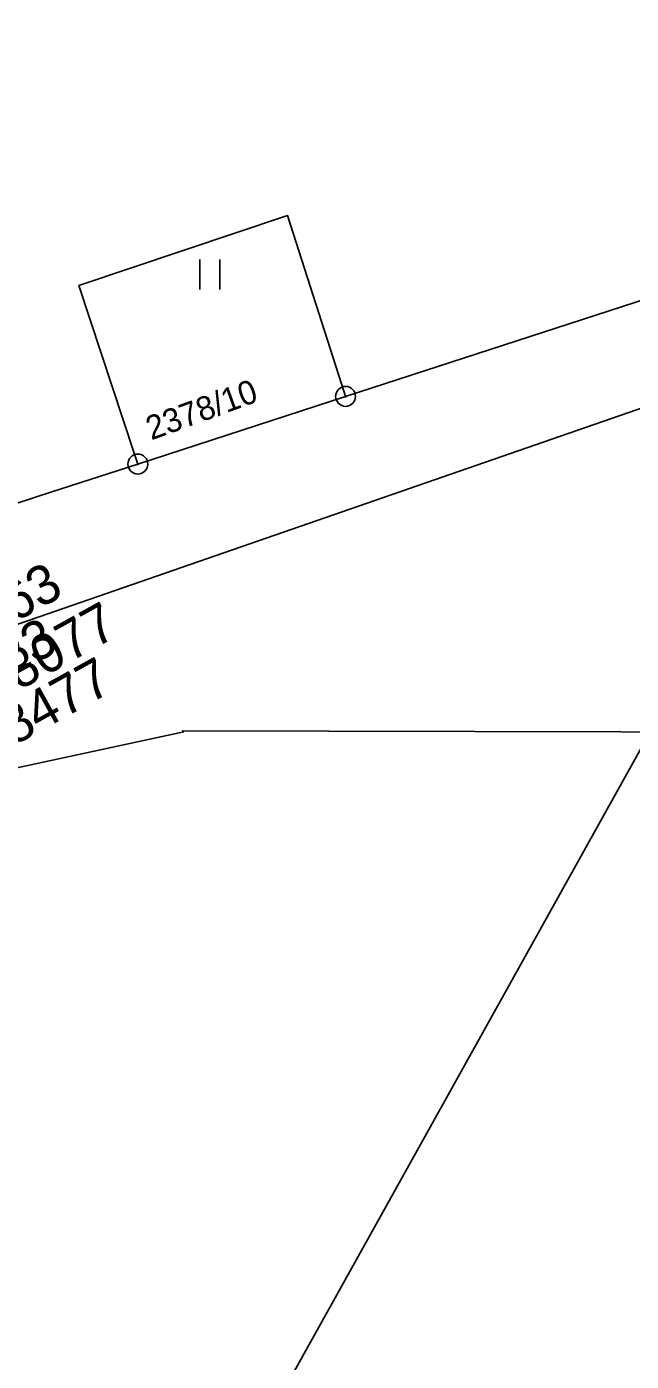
# Model space of a CAD drawing. Extents: x -483721 to -481876, y -1129170 to -1127366.
# Drawn here: x -482169.1 to -482138.7, y -1128251.9 to -1128184.8 of the extents above; entities that cross this region are included whole.
import ezdxf

# ---------------------------------------------------------------- set-up
doc = ezdxf.new("R2010")
doc.units = 0
for name, color, linetype in [('Hranice parcel', 7, 'Continuous'), ('Parcelní čísla', 7, 'Continuous'), ('u_OP_lesa', 7, 'Continuous'), ('u_vytyčení', 7, 'Continuous'), ('Značky bodu BP', 7, 'Continuous'), ('Značky kultur', 7, 'Continuous')]:
    doc.layers.add(name, color=color, linetype=linetype)

msp = doc.modelspace()

# ---------------------------------------------------------------- linework, layer by layer
at = {"layer": 'Hranice parcel'}
for p, q in [((-482153.05, -1128203.36), (-482133.34, -1128196.96)), ((-482132.99, -1128202.16), (-482204.83, -1128227.03)), ((-482163.5, -1128206.76), (-482153.05, -1128203.36)), ((-482167.83, -1128208.16), (-482163.5, -1128206.76)), ((-482194.8, -1128216.93), (-482167.83, -1128208.16)), ((-482186.92, -1128225.75), (-482161.18, -1128220.22))]:
    msp.add_line(p, q, dxfattribs=at)
for points in [[(-482163.5, -1128206.76), (-482163.66, -1128206.27), (-482166.46, -1128197.78), (-482155.97, -1128194.27), (-482153.25, -1128202.73), (-482153.05, -1128203.36)], [(-482161.18, -1128220.22), (-482161.24, -1128220.16), (-482080.46, -1128220.35)]]:
    msp.add_lwpolyline(points, dxfattribs=at)
at = {"layer": 'u_OP_lesa'}
msp.add_lwpolyline([(-482190.249, -1128314.436), (-482117.573, -1128184.051), (-482116.304, -1128170.168), (-482117.883, -1128152.484)], dxfattribs=at)
at = {"layer": 'Značky bodu BP'}
for centre, radius in [((-482153.05, -1128203.36), 0.5), ((-482153.05, -1128203.36), 0.0303), ((-482163.5, -1128206.76), 0.5), ((-482163.5, -1128206.76), 0.0303)]:
    msp.add_circle(centre, radius, dxfattribs=at)
at = {"layer": 'Značky kultur'}
for p, q in [((-482160.381, -1128197.98), (-482160.381, -1128196.48)), ((-482159.38, -1128197.98), (-482159.38, -1128196.48))]:
    msp.add_line(p, q, dxfattribs=at)

# ---------------------------------------------------------------- texts
at = {"layer": 'Parcelní čísla'}
msp.add_text('2378/10', height=1.2, rotation=20, dxfattribs=at).set_placement((-482162.824, -1128205.573))
at = {"layer": 'u_vytyčení'}
for s, p in [('X=-482187.7163', (-482184.249, -1128222.789)), ('Y=-1128224.8077', (-482182.752, -1128225.496)), ('X=-482185.4623', (-482184.509, -1128225.57)), ('Y=-1128223.8477', (-482183.011, -1128228.277))]:
    msp.add_text(s, height=1.96875, rotation=28.95592, dxfattribs=at).set_placement(p)

doc.saveas('drawing.dxf')
